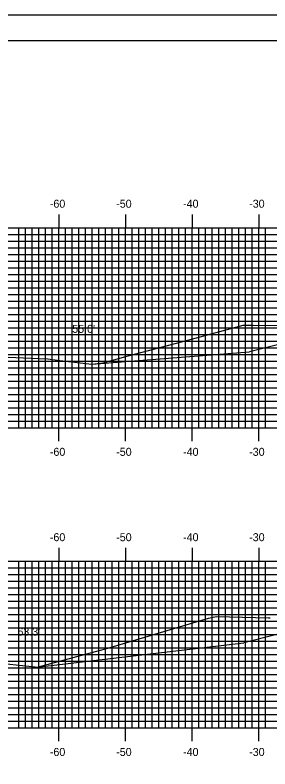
# Model space of a CAD drawing. Extents: x 852540 to 852884, y 364661 to 364881.
# Drawn here: x 852639.7 to 852678, y 364768.2 to 364881.3 of the extents above; entities that cross this region are included whole.
import ezdxf

# ---------------------------------------------------------------- set-up
doc = ezdxf.new("R2010")
doc.units = 0
for name, color, linetype in [('BORDER', 7, 'Continuous'), ('D_Roadway_SlopeLines', 7, 'Continuous'), ('D_Text_Standard', 7, 'Continuous'), ('H_V ANNOTATION', 7, 'Continuous'), ('MAJOR', 7, 'Continuous'), ('MINOR', 7, 'Continuous'), ('PLOT BOUNDARY', 7, 'Continuous'), ('S_Roadway_Centerline', 7, 'Continuous')]:
    doc.layers.add(name, color=color, linetype=linetype)

msp = doc.modelspace()

# ---------------------------------------------------------------- linework, layer by layer
at = {"layer": 'BORDER'}
msp.add_lwpolyline([(852556.67, 364667.37), (852876.67, 364667.37), (852876.67, 364877.37), (852556.67, 364877.37)], close=True, dxfattribs=at)
at = {"layer": 'D_Roadway_SlopeLines'}
for p, q in [((852651.24, 364828.91), (852674.91, 364830.76)), ((852642.99, 364783.5), (852674.06, 364787.15))]:
    msp.add_line(p, q, dxfattribs=at)
for points in [[(852689.13, 364834.31), (852674.91, 364830.76)], [(852688.28, 364790.71), (852674.06, 364787.15)]]:
    msp.add_lwpolyline(points, dxfattribs=at)
at = {"layer": 'MAJOR'}
for p, q in [((852646.27, 364851.37), (852646.27, 364849.37)), ((852656.27, 364851.37), (852656.27, 364849.37)), ((852666.27, 364851.37), (852666.27, 364849.37)), ((852676.27, 364851.37), (852676.27, 364849.37)), ((852566.27, 364849.37), (852846.27, 364849.37)), ((852566.27, 364849.37), (852846.27, 364849.37)), ((852646.27, 364819.37), (852646.27, 364849.37)), ((852656.27, 364819.37), (852656.27, 364849.37)), ((852666.27, 364819.37), (852666.27, 364849.37)), ((852676.27, 364819.37), (852676.27, 364849.37)), ((852566.27, 364844.37), (852846.27, 364844.37)), ((852566.27, 364839.37), (852846.27, 364839.37)), ((852566.27, 364834.37), (852846.27, 364834.37)), ((852566.27, 364829.37), (852846.27, 364829.37)), ((852566.27, 364824.37), (852846.27, 364824.37)), ((852566.27, 364819.37), (852846.27, 364819.37)), ((852566.27, 364819.37), (852846.27, 364819.37)), ((852646.27, 364817.37), (852646.27, 364819.37)), ((852656.27, 364817.37), (852656.27, 364819.37)), ((852666.27, 364817.37), (852666.27, 364819.37)), ((852676.27, 364817.37), (852676.27, 364819.37)), ((852646.27, 364801.37), (852646.27, 364799.37)), ((852656.27, 364801.37), (852656.27, 364799.37)), ((852666.27, 364801.37), (852666.27, 364799.37)), ((852676.27, 364801.37), (852676.27, 364799.37)), ((852566.27, 364799.37), (852846.27, 364799.37)), ((852566.27, 364799.37), (852846.27, 364799.37)), ((852646.27, 364774.37), (852646.27, 364799.37)), ((852656.27, 364774.37), (852656.27, 364799.37)), ((852666.27, 364774.37), (852666.27, 364799.37)), ((852676.27, 364774.37), (852676.27, 364799.37)), ((852566.27, 364794.37), (852846.27, 364794.37)), ((852566.27, 364789.37), (852846.27, 364789.37)), ((852566.27, 364784.37), (852846.27, 364784.37)), ((852566.27, 364779.37), (852846.27, 364779.37)), ((852566.27, 364774.37), (852846.27, 364774.37)), ((852566.27, 364774.37), (852846.27, 364774.37)), ((852646.27, 364772.37), (852646.27, 364774.37)), ((852656.27, 364772.37), (852656.27, 364774.37)), ((852666.27, 364772.37), (852666.27, 364774.37)), ((852676.27, 364772.37), (852676.27, 364774.37))]:
    msp.add_line(p, q, dxfattribs=at)
at = {"layer": 'MINOR'}
for p, q in [((852640.27, 364819.37), (852640.27, 364849.37)), ((852641.27, 364819.37), (852641.27, 364849.37)), ((852642.27, 364819.37), (852642.27, 364849.37)), ((852643.27, 364819.37), (852643.27, 364849.37)), ((852644.27, 364819.37), (852644.27, 364849.37)), ((852645.27, 364819.37), (852645.27, 364849.37)), ((852647.27, 364819.37), (852647.27, 364849.37)), ((852648.27, 364819.37), (852648.27, 364849.37)), ((852649.27, 364819.37), (852649.27, 364849.37)), ((852650.27, 364819.37), (852650.27, 364849.37)), ((852651.27, 364819.37), (852651.27, 364849.37)), ((852652.27, 364819.37), (852652.27, 364849.37)), ((852653.27, 364819.37), (852653.27, 364849.37)), ((852654.27, 364819.37), (852654.27, 364849.37)), ((852655.27, 364819.37), (852655.27, 364849.37)), ((852657.27, 364819.37), (852657.27, 364849.37)), ((852658.27, 364819.37), (852658.27, 364849.37)), ((852659.27, 364819.37), (852659.27, 364849.37)), ((852660.27, 364819.37), (852660.27, 364849.37)), ((852661.27, 364819.37), (852661.27, 364849.37)), ((852662.27, 364819.37), (852662.27, 364849.37)), ((852663.27, 364819.37), (852663.27, 364849.37)), ((852664.27, 364819.37), (852664.27, 364849.37)), ((852665.27, 364819.37), (852665.27, 364849.37)), ((852667.27, 364819.37), (852667.27, 364849.37)), ((852668.27, 364819.37), (852668.27, 364849.37)), ((852669.27, 364819.37), (852669.27, 364849.37)), ((852670.27, 364819.37), (852670.27, 364849.37)), ((852671.27, 364819.37), (852671.27, 364849.37)), ((852672.27, 364819.37), (852672.27, 364849.37)), ((852673.27, 364819.37), (852673.27, 364849.37)), ((852674.27, 364819.37), (852674.27, 364849.37)), ((852675.27, 364819.37), (852675.27, 364849.37)), ((852677.27, 364819.37), (852677.27, 364849.37)), ((852566.27, 364848.37), (852846.27, 364848.37)), ((852566.27, 364847.37), (852846.27, 364847.37)), ((852566.27, 364846.37), (852846.27, 364846.37)), ((852566.27, 364845.37), (852846.27, 364845.37)), ((852566.27, 364843.37), (852846.27, 364843.37)), ((852566.27, 364842.37), (852846.27, 364842.37)), ((852566.27, 364841.37), (852846.27, 364841.37)), ((852566.27, 364840.37), (852846.27, 364840.37)), ((852566.27, 364838.37), (852846.27, 364838.37)), ((852566.27, 364837.37), (852846.27, 364837.37)), ((852566.27, 364836.37), (852846.27, 364836.37)), ((852566.27, 364835.37), (852846.27, 364835.37)), ((852566.27, 364833.37), (852846.27, 364833.37)), ((852566.27, 364832.37), (852846.27, 364832.37)), ((852566.27, 364831.37), (852846.27, 364831.37)), ((852566.27, 364830.37), (852846.27, 364830.37)), ((852566.27, 364828.37), (852846.27, 364828.37)), ((852566.27, 364827.37), (852846.27, 364827.37)), ((852566.27, 364826.37), (852846.27, 364826.37)), ((852566.27, 364825.37), (852846.27, 364825.37)), ((852566.27, 364823.37), (852846.27, 364823.37)), ((852566.27, 364822.37), (852846.27, 364822.37)), ((852566.27, 364821.37), (852846.27, 364821.37)), ((852566.27, 364820.37), (852846.27, 364820.37)), ((852640.27, 364774.37), (852640.27, 364799.37)), ((852641.27, 364774.37), (852641.27, 364799.37)), ((852642.27, 364774.37), (852642.27, 364799.37)), ((852643.27, 364774.37), (852643.27, 364799.37)), ((852644.27, 364774.37), (852644.27, 364799.37)), ((852645.27, 364774.37), (852645.27, 364799.37)), ((852647.27, 364774.37), (852647.27, 364799.37)), ((852648.27, 364774.37), (852648.27, 364799.37)), ((852649.27, 364774.37), (852649.27, 364799.37)), ((852650.27, 364774.37), (852650.27, 364799.37)), ((852651.27, 364774.37), (852651.27, 364799.37)), ((852652.27, 364774.37), (852652.27, 364799.37)), ((852653.27, 364774.37), (852653.27, 364799.37)), ((852654.27, 364774.37), (852654.27, 364799.37)), ((852655.27, 364774.37), (852655.27, 364799.37)), ((852657.27, 364774.37), (852657.27, 364799.37)), ((852658.27, 364774.37), (852658.27, 364799.37)), ((852659.27, 364774.37), (852659.27, 364799.37)), ((852660.27, 364774.37), (852660.27, 364799.37)), ((852661.27, 364774.37), (852661.27, 364799.37)), ((852662.27, 364774.37), (852662.27, 364799.37)), ((852663.27, 364774.37), (852663.27, 364799.37)), ((852664.27, 364774.37), (852664.27, 364799.37)), ((852665.27, 364774.37), (852665.27, 364799.37)), ((852667.27, 364774.37), (852667.27, 364799.37)), ((852668.27, 364774.37), (852668.27, 364799.37)), ((852669.27, 364774.37), (852669.27, 364799.37)), ((852670.27, 364774.37), (852670.27, 364799.37)), ((852671.27, 364774.37), (852671.27, 364799.37)), ((852672.27, 364774.37), (852672.27, 364799.37)), ((852673.27, 364774.37), (852673.27, 364799.37)), ((852674.27, 364774.37), (852674.27, 364799.37)), ((852675.27, 364774.37), (852675.27, 364799.37)), ((852677.27, 364774.37), (852677.27, 364799.37)), ((852566.27, 364798.37), (852846.27, 364798.37)), ((852566.27, 364797.37), (852846.27, 364797.37)), ((852566.27, 364796.37), (852846.27, 364796.37)), ((852566.27, 364795.37), (852846.27, 364795.37)), ((852566.27, 364793.37), (852846.27, 364793.37)), ((852566.27, 364792.37), (852846.27, 364792.37)), ((852566.27, 364791.37), (852846.27, 364791.37)), ((852566.27, 364790.37), (852846.27, 364790.37)), ((852566.27, 364788.37), (852846.27, 364788.37)), ((852566.27, 364787.37), (852846.27, 364787.37)), ((852566.27, 364786.37), (852846.27, 364786.37)), ((852566.27, 364785.37), (852846.27, 364785.37)), ((852566.27, 364783.37), (852846.27, 364783.37)), ((852566.27, 364782.37), (852846.27, 364782.37)), ((852566.27, 364781.37), (852846.27, 364781.37)), ((852566.27, 364780.37), (852846.27, 364780.37)), ((852566.27, 364778.37), (852846.27, 364778.37)), ((852566.27, 364777.37), (852846.27, 364777.37)), ((852566.27, 364776.37), (852846.27, 364776.37)), ((852566.27, 364775.37), (852846.27, 364775.37))]:
    msp.add_line(p, q, dxfattribs=at)
at = {"layer": 'PLOT BOUNDARY'}
msp.add_lwpolyline([(852540.48, 364661.25), (852880.48, 364661.25), (852880.48, 364881.25), (852540.48, 364881.25)], close=True, dxfattribs=at)
at = {"layer": 'S_Roadway_Centerline'}
for points in [[(852635.17, 364830.09), (852643.25, 364829.77), (852644.62, 364829.72), (852646.43, 364829.48), (852651.24, 364828.91), (852652.94, 364829.1), (852656.69, 364830.17), (852665.64, 364832.49), (852673.95, 364834.78), (852675.45, 364834.77), (852679.5, 364834.7)], [(852635.07, 364784.32), (852642.74, 364783.53), (852642.97, 364783.5), (852643.01, 364783.5), (852652.54, 364786.02), (852653.29, 364786.25), (852654.48, 364786.57), (852668.73, 364790.85), (852669.94, 364791.06), (852677.72, 364790.88), (852677.99, 364790.87)]]:
    msp.add_lwpolyline(points, dxfattribs=at)

# ---------------------------------------------------------------- texts
at = {"layer": 'D_Text_Standard'}
for s, p in [("55.0'", (852648.28, 364833.61)), ("63.3'", (852640.05, 364788.21))]:
    msp.add_text(s, height=1.2, dxfattribs=at).set_placement(p)
at = {"layer": 'H_V ANNOTATION'}
for s, p in [('-60', (852644.92, 364852.37)), ('-50', (852654.88, 364852.37)), ('-40', (852664.92, 364852.37)), ('-30', (852674.84, 364852.37)), ('-60', (852644.92, 364815.17)), ('-50', (852654.88, 364815.17)), ('-40', (852664.92, 364815.17)), ('-30', (852674.84, 364815.17)), ('-60', (852644.92, 364802.37)), ('-50', (852654.88, 364802.37)), ('-40', (852664.92, 364802.37)), ('-30', (852674.84, 364802.37)), ('-60', (852644.92, 364770.17)), ('-50', (852654.88, 364770.17)), ('-40', (852664.92, 364770.17)), ('-30', (852674.84, 364770.17))]:
    msp.add_text(s, height=1.2, dxfattribs=at).set_placement(p)

doc.saveas('drawing.dxf')
